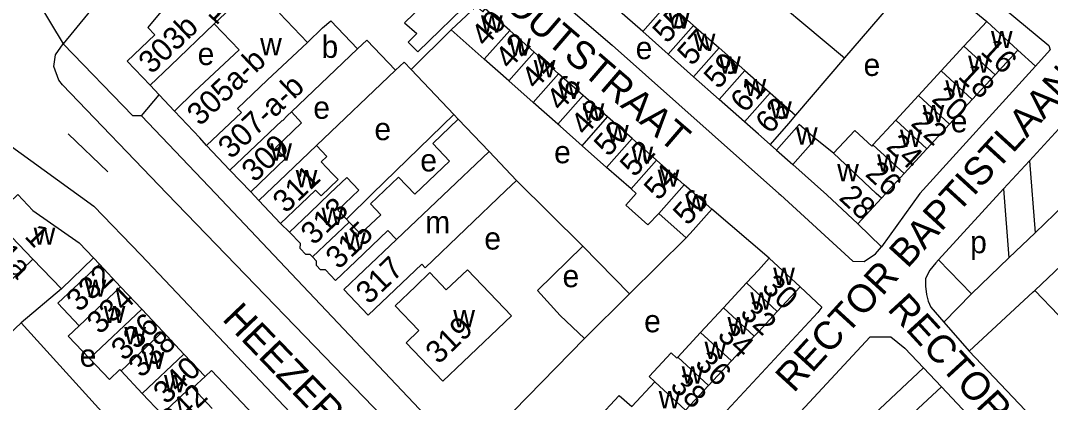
# Model space of a CAD drawing. Extents: x 161258 to 163262, y 380749 to 382054.
# Drawn here: x 162868.3 to 163052.1, y 381462.7 to 381530.8 of the extents above; entities that cross this region are included whole.
import ezdxf

# ---------------------------------------------------------------- set-up
doc = ezdxf.new("R2010")
doc.units = 0
for name, color, linetype in [('BLT_Basislijn', 7, 'Continuous'), ('BLT_Bebouwing', 7, 'Continuous'), ('BLT_Centroide', 7, 'Continuous'), ('BLT_Huisnummer', 7, 'Continuous'), ('BLT_Huisnummer_ tussenligend', 7, 'Continuous'), ('BLT_Huisnummer_reeks', 7, 'Continuous'), ('BLT_Onderverdeling_panden', 7, 'Continuous'), ('BLT_Straatnaam', 7, 'Continuous'), ('BLT_Vlakafsluiter', 7, 'Continuous')]:
    doc.layers.add(name, color=color, linetype=linetype)

msp = doc.modelspace()

# ---------------------------------------------------------------- linework, layer by layer
at = {"layer": 'BLT_Basislijn'}
for p, q in [((162895.92, 381551.25), (162875.83, 381526.71)), ((163024.68, 381535.05), (163015.39, 381524.18)), ((163035.04, 381535.44), (163040.75, 381530.7)), ((163015.39, 381524.18), (163006.64, 381513.95)), ((163049.44, 381522.72), (163046.3, 381525.6)), ((162921.07, 381508.55), (162935.2, 381522.03)), ((162893.02, 381517.61), (162891.39, 381519.35)), ((162889.86, 381513.88), (162893.02, 381517.61)), ((162895.75, 381514.66), (162893.02, 381517.61)), ((162946.4, 381513.25), (162945.59, 381514.11)), ((163053.63, 381511.53), (163048.39, 381505.82)), ((162876.74, 381510.66), (162883.85, 381503.87)), ((163067.69, 381510.57), (163049.4, 381493)), ((163003.24, 381507.71), (163002.07, 381508.76)), ((163048.39, 381505.82), (163043.77, 381500.8)), ((163048.39, 381505.82), (163049.4, 381493)), ((162968.64, 381490.6), (162956.8, 381502.33)), ((162909.35, 381500.28), (162910.78, 381498.74)), ((163043.77, 381500.8), (163032.16, 381488.17)), ((163043.77, 381500.8), (163044.73, 381488.52)), ((163001.94, 381488.43), (162991.66, 381497.22)), ((162916.28, 381493.11), (162914.69, 381494.64)), ((163021.97, 381490.49), (163017.75, 381494.6)), ((163049.4, 381493), (163044.73, 381488.52)), ((162976.98, 381482.08), (162987.12, 381492.09)), ((162968.64, 381490.6), (162976.98, 381482.08)), ((162881.3, 381488.49), (162882.35, 381487.37)), ((163032.16, 381488.17), (163031.67, 381487.64)), ((163032.16, 381488.17), (163038.04, 381482.1)), ((163044.73, 381488.52), (163038.04, 381482.1)), ((163049.32, 381482.68), (163054.05, 381487.16)), ((162875.54, 381482.96), (162868.34, 381476.9)), ((162968.92, 381474.14), (162976.98, 381482.08)), ((163038.04, 381482.1), (163033.07, 381477.02)), ((163053.59, 381478.28), (163049.32, 381482.68)), ((163030.8, 381479.74), (163033.07, 381477.02)), ((162868.34, 381476.9), (162887.92, 381455.42)), ((163033.07, 381477.02), (163037.63, 381471.89)), ((162981.27, 381432.92), (163019.94, 381474.4)), ((162968.92, 381474.14), (162952.2, 381457.05)), ((163029.47, 381468.86), (163032.66, 381465.51)), ((163003.34, 381438.36), (163032.66, 381465.51)), ((163032.66, 381465.51), (163047.6, 381449.79))]:
    msp.add_line(p, q, dxfattribs=at)
for points in [[(162944.72, 381609.34), (162946.07, 381610.82), (162947.99, 381611.88), (162948.82, 381611.97), (162950.63, 381611.39), (162950.79, 381611.07), (162957.1, 381606.01), (162961.96, 381601.6), (163026.21, 381547.71), (163051.87, 381526.38), (163052.07, 381525.64), (163049.44, 381522.72)], [(162960.26, 381571.07), (162974.82, 381558.53), (162994.78, 381541.72), (162997.57, 381539.11), (163015.39, 381524.18)], [(162943.6, 381552.94), (162950.87, 381546.87), (162957.39, 381540.62), (162973.86, 381526.45), (163003.62, 381500.02), (163003.93, 381499.74), (163016.85, 381487.94), (163018.85, 381487.86), (163020.89, 381489.24), (163021.97, 381490.49)], [(162938.02, 381522.12), (162945.11, 381529.21)], [(162960.18, 381431.55), (162951.7, 381440.3), (162934.79, 381458.21), (162894.35, 381500), (162875.72, 381519.36), (162875.08, 381520.24), (162874.2, 381522.63), (162874.48, 381524.75), (162875.83, 381526.71)], [(162889.86, 381513.88), (162888.31, 381513.84), (162875.83, 381526.71)], [(162935.2, 381522.03), (162930.05, 381527.36), (162928.43, 381525.82)], [(162935.2, 381522.03), (162936.73, 381523.41), (162938.02, 381522.12)], [(162945.59, 381514.11), (162938.02, 381522.12)], [(163049.44, 381522.72), (163028.84, 381500), (163021.97, 381490.49)], [(162947.79, 381452.69), (162903.07, 381500), (162889.86, 381513.88)], [(162926.44, 381495.42), (162931.09, 381500), (162945.59, 381514.11)], [(162863.18, 381507.79), (162864.75, 381508.84), (162865.97, 381508.87), (162881.31, 381497.75)], [(162881.31, 381497.75), (162889.71, 381489.05), (162960.14, 381414.78)], [(162968.64, 381490.6), (162960.53, 381482.71), (162964.62, 381478.2), (162968.92, 381474.14)], [(163031.67, 381487.64), (163030.58, 381486.31), (163029.82, 381484.82), (163029.82, 381483.46), (163030.02, 381482), (163030.28, 381480.81), (163030.8, 381479.74)], [(163007.42, 381483.36), (163011.32, 381479.7), (163010.63, 381478.79), (162970.35, 381435.48)], [(163037.63, 381471.89), (163049.05, 381482.42), (163049.32, 381482.68)], [(162818.14, 381437.82), (162830.11, 381449.08), (162834.18, 381444.76), (162868.34, 381476.9)], [(163019.94, 381474.4), (163023.65, 381474.4), (163026.11, 381472.4), (163029.47, 381468.86)], [(163076.04, 381437.02), (163073.3, 381434.35), (163037.63, 381471.89)], [(162981.27, 381432.92), (162985.55, 381428.37), (162986.82, 381428.43), (162994.34, 381435.96), (163029.47, 381468.86)], [(162937.87, 381428.43), (162939.15, 381429.64), (162902.37, 381468.44), (162901.21, 381467.34)]]:
    msp.add_lwpolyline(points, dxfattribs=at)
at = {"layer": 'BLT_Bebouwing'}
for p, q in [((162983.88, 381534.02), (162988.43, 381530)), ((162914.51, 381532.18), (162919.47, 381526.94)), ((162955.59, 381529.09), (162951.22, 381532.95)), ((162979.33, 381528.88), (162974.78, 381532.9)), ((162919.47, 381526.94), (162922.16, 381529.56)), ((162988.43, 381530), (162992.99, 381525.98)), ((163040.75, 381530.7), (163036.69, 381526.3)), ((163046.3, 381525.6), (163040.75, 381530.7)), ((162951.05, 381523.96), (162945.11, 381529.21)), ((162959.95, 381525.23), (162955.59, 381529.09)), ((162983.88, 381524.85), (162979.33, 381528.88)), ((162916.6, 381514.57), (162928.43, 381525.82)), ((162992.99, 381525.98), (162997.54, 381521.97)), ((163036.69, 381526.3), (163032.63, 381521.89)), ((162955.42, 381520.1), (162951.05, 381523.96)), ((162964.32, 381521.37), (162959.95, 381525.23)), ((162988.42, 381520.83), (162983.88, 381524.85)), ((163042.24, 381521.18), (163046.3, 381525.6)), ((162968.69, 381517.51), (162964.32, 381521.37)), ((162992.97, 381516.8), (162988.42, 381520.83)), ((162997.54, 381521.97), (163002.1, 381517.95)), ((163032.63, 381521.89), (163028.57, 381517.49)), ((163038.18, 381516.78), (163042.24, 381521.18)), ((162959.79, 381516.24), (162955.42, 381520.1)), ((162973.06, 381513.65), (162968.69, 381517.51)), ((162997.52, 381512.78), (162992.97, 381516.8)), ((163002.1, 381517.95), (163006.64, 381513.95)), ((163028.57, 381517.49), (163024.51, 381513.08)), ((163034.12, 381512.37), (163038.18, 381516.78)), ((162964.16, 381512.38), (162959.79, 381516.24)), ((162916.6, 381514.57), (162918.41, 381512.63)), ((162946.4, 381513.25), (162951.89, 381507.48)), ((162977.43, 381509.79), (162973.06, 381513.65)), ((163024.51, 381513.08), (163020.45, 381508.68)), ((162964.58, 381512.01), (162964.16, 381512.38)), ((162968.52, 381508.52), (162964.58, 381512.01)), ((163000, 381510.58), (162997.52, 381512.78)), ((163030.07, 381507.96), (163034.12, 381512.37)), ((162981.79, 381505.93), (162977.43, 381509.79)), ((163002.07, 381508.76), (163000, 381510.58)), ((163013.42, 381507.17), (163010.17, 381509.76)), ((162901.47, 381508.55), (162905.64, 381504.17)), ((162972.89, 381504.66), (162968.52, 381508.52)), ((163003.24, 381507.71), (163006.11, 381505.15)), ((163026.01, 381503.55), (163030.07, 381507.96)), ((162986.73, 381501.57), (162981.79, 381505.93)), ((162905.64, 381504.17), (162909.35, 381500.28)), ((162977.26, 381500.8), (162972.89, 381504.66)), ((163006.11, 381505.15), (163012.2, 381499.73)), ((162914.69, 381494.64), (162910.78, 381498.74)), ((163012.2, 381499.73), (163017.75, 381494.6)), ((163021.96, 381499.15), (163017.75, 381494.6)), ((162987.12, 381492.09), (162982.2, 381496.44)), ((162926.44, 381495.42), (162926.94, 381494.9)), ((162866.55, 381484.52), (162870.45, 381488.26)), ((162875.54, 381482.96), (162870.45, 381488.26)), ((162881.3, 381488.49), (162875.54, 381482.96)), ((162882.35, 381487.37), (162886.12, 381483.36)), ((163000, 381486.33), (163001.94, 381488.43)), ((163001.94, 381488.43), (163007.42, 381483.36)), ((162997.86, 381484.03), (163000, 381486.33)), ((162993.77, 381479.62), (162997.86, 381484.03)), ((162886.12, 381483.36), (162889.89, 381479.36)), ((162930.33, 381478.28), (162925.96, 381482.86)), ((163007.42, 381483.36), (163003.34, 381478.95)), ((162889.89, 381479.36), (162893.66, 381475.35)), ((162989.68, 381475.21), (162993.77, 381479.62)), ((163003.34, 381478.95), (163000, 381475.34)), ((162893.66, 381475.35), (162897.43, 381471.35)), ((162937.11, 381473.36), (162939.38, 381475.53)), ((162985.6, 381470.8), (162989.68, 381475.21)), ((162999.26, 381474.54), (162995.17, 381470.13)), ((163000, 381475.34), (162999.26, 381474.54)), ((162897.43, 381471.35), (162901.21, 381467.34)), ((162995.17, 381470.13), (162991.08, 381465.72)), ((162886.21, 381468.34), (162889.98, 381464.32)), ((162901.21, 381467.34), (162899.03, 381465.29)), ((162899.03, 381465.29), (162902.46, 381461.65)), ((162977.42, 381461.99), (162981.51, 381466.39)), ((162991.08, 381465.72), (162987, 381461.31)), ((162893.45, 381460.61), (162889.98, 381464.32))]:
    msp.add_line(p, q, dxfattribs=at)
for points in [[(162945.08, 381538.5), (162936.81, 381530.43), (162938.99, 381528.52), (162937.46, 381527.03), (162939.16, 381525.28), (162949.1, 381534.98)], [(162893.88, 381533.1), (162890.96, 381529.62), (162892.21, 381528.32), (162887.3, 381523.64), (162891.39, 381519.35)], [(162945.11, 381529.21), (162949.64, 381533.43), (162950.77, 381532.44), (162951.22, 381532.95)], [(162891.39, 381519.35), (162895.01, 381522.8), (162902.83, 381530.27)], [(162895.75, 381514.66), (162899.33, 381518.17), (162907.26, 381525.64), (162902.83, 381530.27)], [(162922.16, 381529.56), (162923.63, 381530.82), (162928.43, 381525.82)], [(162901.47, 381508.55), (162900.27, 381509.93), (162895.75, 381514.66)], [(162932.58, 381496.21), (162930.73, 381498.15), (162935.74, 381502.9), (162938.65, 381499.85), (162944.86, 381505.74), (162941.84, 381508.89), (162946.4, 381513.25)], [(163006.64, 381513.95), (163005.38, 381512.51), (163002.07, 381508.76)], [(162909.35, 381500.28), (162915.58, 381506.22), (162913.74, 381508.16), (162918.41, 381512.63)], [(163010.17, 381509.76), (163007.29, 381512.3), (163003.24, 381507.71)], [(163020.45, 381508.68), (163020.23, 381508.44), (163017.18, 381511.25), (163013.42, 381507.17)], [(162910.78, 381498.74), (162912.1, 381500), (162914.4, 381502.19), (162921.07, 381508.55)], [(162921.07, 381508.55), (162922.92, 381506.61), (162921.91, 381505.66), (162923.97, 381503.5), (162924.95, 381502.48), (162921.9, 381499.57), (162920.94, 381500.6), (162918.31, 381498.09), (162914.69, 381494.64)], [(162951.89, 381507.48), (162956.8, 381502.33)], [(162916.28, 381493.11), (162919.9, 381496.56), (162923.5, 381500), (162925.57, 381501.98), (162926.49, 381502.85), (162928.64, 381500.6), (162924.9, 381497.04), (162926.44, 381495.42)], [(162956.8, 381502.33), (162954.92, 381500.53), (162940.5, 381486.76)], [(163026.01, 381503.55), (163022.74, 381500), (163021.96, 381499.15)], [(162982.2, 381496.44), (162980.26, 381494.4), (162976.3, 381497.89), (162978.17, 381500), (162977.26, 381500.8)], [(162991.66, 381497.22), (162988.51, 381500), (162986.73, 381501.57)], [(162863.36, 381495.66), (162867.77, 381499.82), (162870.45, 381496.97), (162878.7, 381491.19), (162881.3, 381488.49)], [(162991.66, 381497.22), (162988.35, 381493.47), (162987.12, 381492.09)], [(162926.94, 381494.9), (162928.97, 381492.77), (162932.58, 381496.21)], [(162920.4, 381488.67), (162919.98, 381489.11), (162919.21, 381489.13), (162918.19, 381490.2), (162918.21, 381491.09), (162916.28, 381493.11)], [(162935.37, 381491.8), (162933.84, 381493.4), (162928.12, 381487.93), (162924.5, 381484.48)], [(162925.96, 381482.86), (162929.58, 381486.31), (162935.37, 381491.8)], [(162882.35, 381487.37), (162874.91, 381480.4), (162878.69, 381476.37), (162878.69, 381476.37)], [(162924.5, 381484.48), (162922.71, 381486.36), (162921.8, 381486.38), (162921.09, 381487.13), (162921.1, 381487.93), (162920.4, 381488.67)], [(162940.5, 381486.76), (162939.89, 381487.41), (162930.33, 381478.28)], [(162939.38, 381475.53), (162935.13, 381479.97), (162938.75, 381483.43), (162941.33, 381485.89), (162944.27, 381482.81)], [(162944.27, 381482.81), (162948.03, 381486.39), (162955.89, 381478.16), (162947.27, 381469.94), (162943.66, 381466.49), (162937.11, 381473.36)], [(162878.69, 381476.37), (162876.77, 381474.56), (162880.55, 381470.56)], [(162981.51, 381466.39), (162980.48, 381467.33), (162984.43, 381471.58), (162985.44, 381470.64), (162985.6, 381470.8)], [(162880.55, 381470.56), (162884.12, 381466.83), (162885.99, 381468.58), (162886.21, 381468.34)], [(162973.33, 381457.58), (162971.17, 381459.67), (162975.16, 381463.97), (162977.42, 381461.99)]]:
    msp.add_lwpolyline(points, dxfattribs=at)
at = {"layer": 'BLT_Onderverdeling_panden'}
for p, q in [((162909.82, 381536.92), (162902.83, 381530.27)), ((162979.33, 381528.88), (162983.88, 381534.02)), ((162983.88, 381524.85), (162988.43, 381530)), ((162951.05, 381523.96), (162955.59, 381529.09)), ((162988.42, 381520.83), (162992.99, 381525.98)), ((163042.24, 381521.18), (163036.69, 381526.3)), ((162955.42, 381520.1), (162959.95, 381525.23)), ((162959.79, 381516.24), (162964.32, 381521.37)), ((162992.97, 381516.8), (162997.54, 381521.97)), ((163038.18, 381516.78), (163032.63, 381521.89)), ((162964.16, 381512.38), (162968.69, 381517.51)), ((162997.52, 381512.78), (163002.1, 381517.95)), ((163034.12, 381512.37), (163028.57, 381517.49)), ((162968.52, 381508.52), (162973.06, 381513.65)), ((163030.07, 381507.96), (163024.51, 381513.08)), ((162972.89, 381504.66), (162977.43, 381509.79)), ((163010.17, 381509.76), (163006.11, 381505.15)), ((162935.37, 381491.8), (162951.89, 381507.48)), ((163026.01, 381503.55), (163020.45, 381508.68)), ((162977.26, 381500.8), (162981.79, 381505.93)), ((163021.04, 381500), (163013.42, 381507.17)), ((162982.2, 381496.44), (162986.73, 381501.57)), ((163021.96, 381499.15), (163021.04, 381500)), ((162870.45, 381488.26), (162863.36, 381495.66)), ((162926.94, 381494.9), (162920.4, 381488.67)), ((163003.34, 381478.95), (162997.86, 381484.03)), ((162878.69, 381476.37), (162886.12, 381483.36)), ((162889.89, 381479.36), (162880.55, 381470.56)), ((162999.26, 381474.54), (162993.77, 381479.62)), ((162886.21, 381468.34), (162893.66, 381475.35)), ((162995.17, 381470.13), (162989.68, 381475.21)), ((162897.43, 381471.35), (162889.98, 381464.32)), ((162991.08, 381465.72), (162985.6, 381470.8)), ((162987, 381461.31), (162981.51, 381466.39))]:
    msp.add_line(p, q, dxfattribs=at)
for points in [[(162919.47, 381526.94), (162912.28, 381520.22), (162907, 381515.18), (162907.68, 381514.47), (162901.47, 381508.55)], [(162905.64, 381504.17), (162914.97, 381513.01), (162915, 381512.98), (162915.91, 381513.9), (162916.6, 381514.57)], [(162893.45, 381460.61), (162898.75, 381465.58), (162898.75, 381465.58), (162899.03, 381465.29)]]:
    msp.add_lwpolyline(points, dxfattribs=at)
at = {"layer": 'BLT_Vlakafsluiter'}
msp.add_line((162871.35, 381534.22), (162875.83, 381526.71), dxfattribs=at)

# ---------------------------------------------------------------- texts
at = {"layer": 'BLT_Centroide'}
for s, p in [('w', (162950.46, 381528.69)), ('w', (162983.88, 381529.42)), ('w', (162911.03, 381524.65)), ('b', (162921.99, 381524.2)), ('w', (162955.5, 381524.59)), ('w', (162988.44, 381525.42)), ('w', (163041.51, 381525.94)), ('e', (162899.87, 381522.92)), ('e', (162978.08, 381523.98)), ('w', (162992.98, 381521.39)), ('e', (163018.77, 381520.97)), ('w', (163037.44, 381521.53)), ('w', (162959.88, 381520.73)), ('w', (162997.53, 381517.38)), ('w', (162964.23, 381516.88)), ('w', (163033.38, 381517.12)), ('e', (162920.52, 381513.33)), ('w', (162968.61, 381513.02)), ('w', (163002.08, 381513.36)), ('w', (163029.32, 381512.72)), ('e', (163034.34, 381510.91)), ('e', (162931.43, 381509.52)), ('w', (162972.97, 381509.16)), ('w', (163006.7, 381508.73)), ('w', (163025.27, 381508.31)), ('w', (162912.85, 381505.88)), ('e', (162963.52, 381505.39)), ('w', (162977.34, 381505.3)), ('e', (162939.62, 381503.94)), ('w', (163021.2, 381503.91)), ('w', (162917.38, 381501.12)), ('w', (162982, 381501.19)), ('w', (163014.06, 381502.19)), ('w', (162986.92, 381496.83)), ('w', (162922, 381494.38)), ('m', (162940.5, 381492.88)), ('w', (162870.59, 381490.84)), ('w', (162926.03, 381490)), ('e', (162951.05, 381489.99)), ('p', (163037.8, 381489.34)), ('e', (162965.02, 381483.27)), ('w', (163002.64, 381483.69)), ('w', (162879.7, 381481.56)), ('w', (162998.56, 381479.28)), ('w', (162883.1, 381476.87)), ('w', (162945.52, 381476.12)), ('e', (162979.59, 381475.23)), ('w', (162994.47, 381474.88)), ('w', (162886.78, 381473.09)), ('w', (162990.38, 381470.47)), ('e', (162878.81, 381469.09)), ('w', (162890.09, 381468.67)), ('w', (162986.3, 381466.06)), ('w', (162893.86, 381464.53)), ('w', (162982.2, 381461.66))]:
    msp.add_text(s, height=4, dxfattribs=at).set_placement(p)
at = {"layer": 'BLT_Huisnummer'}
for s, rotation, p in [('40', 48.5361, (162951.3, 381525.99)), ('57', 48.4908, (162988.12, 381522.61)), ('16', 317.3258, (163039.46, 381525.15)), ('44', 48.5354, (162960.28, 381518.39)), ('20', 317.3241, (163030.74, 381516.63)), ('48', 48.5354, (162969.09, 381510.13)), ('63', 48.5986, (163002.09, 381510.44)), ('309', 43.655, (162910.05, 381501.83)), ('52', 48.5348, (162977.88, 381502.75)), ('24', 317.3262, (163022.63, 381508.14)), ('56', 48.5359, (162987.38, 381494.12)), ('28', 317.288, (163014.19, 381499.04)), ('313', 43.6712, (162920.61, 381490.62)), ('1', 313.6052, (162868.8, 381492.24)), ('1a', 313.6052, (162863.61, 381488.8)), ('332', 43.6052, (162878.74, 381478.69)), ('317', 43.6759, (162930.45, 381480.06)), ('30', 317.1882, (163000.38, 381483.04)), ('334', 43.6052, (162882.41, 381474.69)), ('319', 43.6682, (162942.89, 381469.38)), ('34', 317.1857, (162992.48, 381474.45)), ('338', 43.6052, (162889.82, 381466.95)), ('38', 317.1884, (162984.03, 381465.42)), ('342', 43.6052, (162895.47, 381457.37))]:
    msp.add_text(s, height=4, rotation=rotation, dxfattribs=at).set_placement(p)
at = {"layer": 'BLT_Huisnummer_ tussenligend'}
for s, rotation, p in [('55', 48.4966, (162983.7, 381526.6)), ('42', 48.5361, (162955.61, 381521.97)), ('59', 48.4908, (162992.86, 381518.46)), ('18', 317.3258, (163035.45, 381520.7)), ('46', 48.5354, (162964.73, 381514.51)), ('61', 48.4908, (162997.61, 381514.21)), ('50', 48.5354, (162973.24, 381506.39)), ('22', 317.3241, (163027.02, 381512.31)), ('26', 317.3262, (163018.9, 381503.26)), ('311', 43.655, (162915.61, 381496.32)), ('54', 48.5348, (162982.17, 381498.58)), ('315', 43.6712, (162925.06, 381486.31)), ('32', 317.1882, (162996.52, 381478.44)), ('336', 43.6052, (162886.75, 381469.97)), ('340', 43.6052, (162894.27, 381462.22)), ('36', 317.1857, (162988.46, 381469.42))]:
    msp.add_text(s, height=4, rotation=rotation, dxfattribs=at).set_placement(p)
at = {"layer": 'BLT_Huisnummer_reeks'}
for s, rotation, p in [('101', 317.7701, (162897.07, 381535.99)), ('303b', 43.655, (162891.64, 381521.16)), ('305a-b', 43.655, (162900.3, 381511.89)), ('307-a-b', 43.655, (162905.85, 381506))]:
    msp.add_text(s, height=4, rotation=rotation, dxfattribs=at).set_placement(p)
at = {"layer": 'BLT_Straatnaam'}
for s, height, rotation, p in [('ST ROMBOUTSTRAAT', 4.9999, 319.3295, (162931.22, 381553.34)), ('RECTOR BAPTISTLAAN', 5, 47.5531, (163006.29, 381464.28)), ('RECTOR BAPTISTLAAN', 5, 312.5531, (163022.85, 381479.28)), ('HEEZERWEG', 5, 313.8884, (162904.07, 381477.49))]:
    msp.add_text(s, height=height, rotation=rotation, dxfattribs=at).set_placement(p)

doc.saveas('drawing.dxf')
